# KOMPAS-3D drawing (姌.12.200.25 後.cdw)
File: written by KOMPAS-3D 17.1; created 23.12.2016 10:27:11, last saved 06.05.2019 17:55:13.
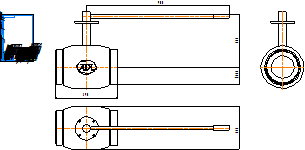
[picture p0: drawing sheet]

Sheet 1: A4, portrait

Title block, sheet 1: name: КШ.12.200.25 сс; material: Внимание! Данный продукт является объектом авторского права ООО «Торговый Дом АДЛ». / Запрещается изменение, копирование, распространение / (в том числе путем копирования на другие сайты и ресурсы в Интернете) / или любое иное использование информации и объектов без предварительного / согласия правообладателя (ООО «Торговый Дом АДЛ»).; sheets: 1; organisation: ООО "Торговый дом АДЛ"; sheet format: A4; stored path: C:\Users\tra\Desktop\2д чертежи\Шаровые краны БИВАЛ\КШ_Бивал_серия_11_12\KOMPAS_2D\КШ.12.200.25 сс.cdw

Views: Вид 1, Проекционный вид 2, Проекционный вид 3
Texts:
  Klimkovich
  ADL
Dimensions and other numbers on the sheet: 390; 900; 336; 109,5; 273; 1:1; 1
